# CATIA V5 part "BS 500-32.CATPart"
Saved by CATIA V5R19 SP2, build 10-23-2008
Part number: BS 500-32
Bounding box of the stored display mesh (mm): x -18.951 to 18.951, y -18.952 to 18.952, z 0 to 94
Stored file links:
  C:\Users\Bora\Desktop\3D Katı model\BS serisi\BS 500\BS 500-32.CATPart
  C:\Program Files\Dassault Systemes\B19\intel_a\reffiles\standard\MetricThickPitch.txt
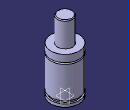
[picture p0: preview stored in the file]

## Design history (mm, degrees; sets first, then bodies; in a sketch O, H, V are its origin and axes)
Body1 (main body)
  Sketch1 on yz-plane, origin (0, 0, 0), H (0, 1, 0), V (0, 0, 1)
    point P1 (10, 93)
    point P3 (10, 93)
    point P5 (19, 51.5)
    point P6 (19, 49.5)
    point P9 (19, 51.5)
    point P14 (19, 49.5)
    line L1 (10, 93) -> (10, 61)
    arc A1 centre (9, 93) radius 1 from (10, 93) to (9, 94) ccw
    arc A2 centre (19, 50.5) radius 1 from (19, 51.5) to (19, 49.5) ccw
    line L2 (19, 0) -> (19, 4)
    line L3 (19, 51.5) -> (19, 61)
    line L4 (17, 7.5) -> (17, 4)
    line L5 (19, 7.5) -> (19, 49.5)
    line L6 (9, 94) -> (0, 94)
    point P15 (0, 94)
    line L7 (10, 61) -> (19, 61)
    line L8 (0, 0) -> (19, 0)
    line L9 (17, 7.5) -> (19, 7.5)
    line L10 (17, 4) -> (19, 4)
    coincidence: P15 V, P1 P3, P5 P9, P6 P14
    tangency: L6 A1
    horizontal: L7 H, L8 H, L9 H, L10 H
  Shaft1: profile Sketch1, axis Sketch1.V, angle 360
  Sketch2 on face of Shaft1 from Sketch1.L8, origin (0, 0, 0), H (1, 0, 0), V (0, -1, 0)
    point P1 (0, 0)
  Hole1: placed by Sketch2, at (0, 0, 0) direction (0, 0, 1), diameter 6.647, depth 4, threaded "M8", thread diameter 8, thread depth 4, pitch 1.25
